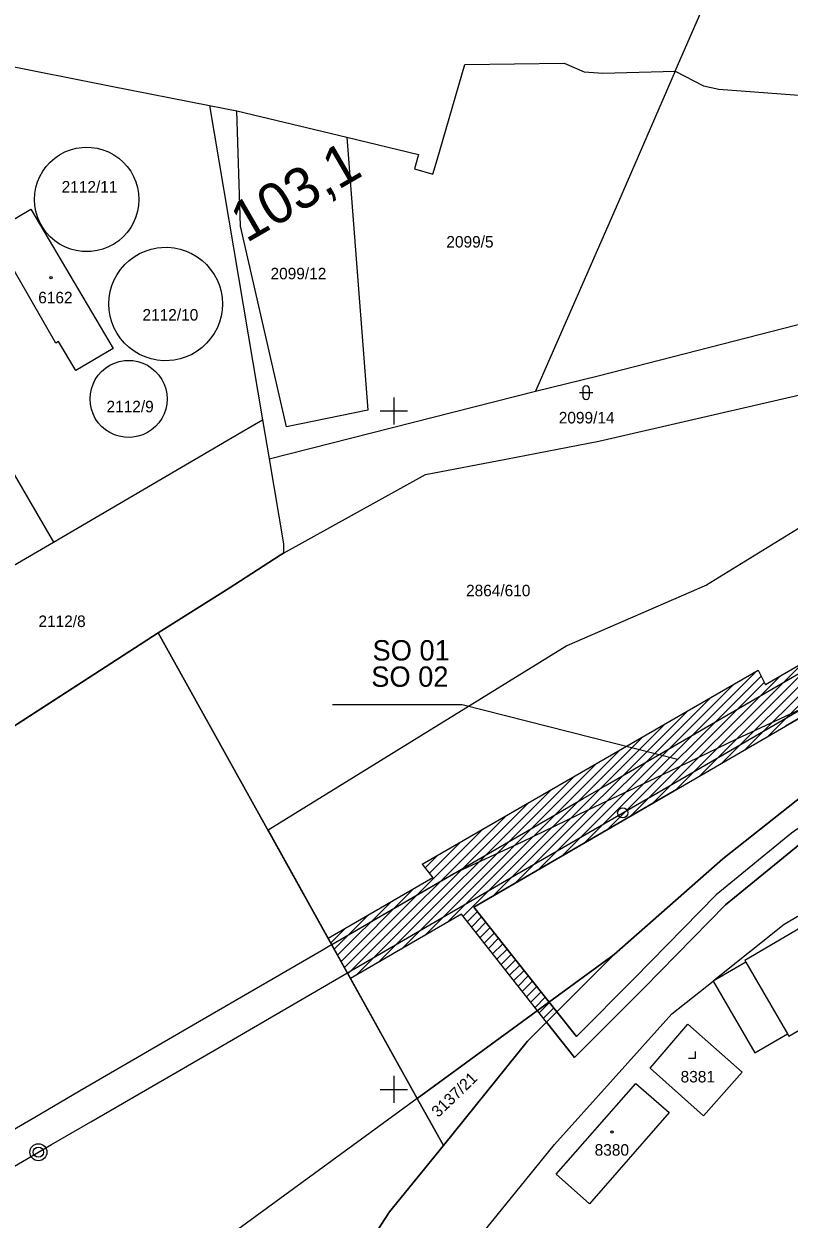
# Model space of a CAD drawing. Extents: x -566165 to -565287, y -1203064 to -1202391.
# Drawn here: x -565854.5 to -565741.8, y -1202819.1 to -1202643 of the extents above; entities that cross this region are included whole.
import ezdxf

# ---------------------------------------------------------------- set-up
doc = ezdxf.new("R2010")
doc.units = 0
for name, color, linetype in [('CD', 7, 'Continuous'), ('Hranice parcel', 7, 'Continuous'), ('Parcelní čísla', 7, 'Continuous'), ('Popis PS SO', 7, 'Continuous'), ('SZDC', 7, 'Continuous'), ('VBř', 7, 'Continuous'), ('Vnitřní kresba', 7, 'Continuous'), ('Vrstva 1', 7, 'Continuous'), ('Vrstva 5', 7, 'Continuous'), ('Vrstva 7', 7, 'Continuous'), ('Značky budov', 7, 'Continuous'), ('Značky kultur', 7, 'Continuous'), ('ČD dotčená část', 7, 'Continuous'), ('ČD pro SŽDC', 7, 'Continuous')]:
    doc.layers.add(name, color=color, linetype=linetype)

msp = doc.modelspace()

# ---------------------------------------------------------------- linework, layer by layer
at = {"layer": 'CD'}
for p, q in [((-565767.54, -1202780.11), (-565775.99, -1202788.56)), ((-565775.99, -1202788.56), (-565777.51, -1202790.08))]:
    msp.add_line(p, q, dxfattribs=at)
for points in [[(-565834.73, -1202732.72), (-565824.28, -1202726.13), (-565816.76, -1202721.27), (-565816.24, -1202720.98), (-565795.32, -1202709.38), (-565783.5, -1202707.11), (-565769.79, -1202704.47), (-565716.98, -1202692.29), (-565668.65, -1202665.75), (-565651.82, -1202653.08), (-565584.94, -1202616.47), (-565582.08, -1202612.99), (-565579.05, -1202609.31), (-565569.85, -1202598.11), (-565567.82, -1202597.46), (-565565.95, -1202596.85), (-565564.75, -1202597.63), (-565564, -1202597.36)], [(-565608.23, -1202688.5), (-565651.3, -1202717.76), (-565670.03, -1202715.16), (-565703.34, -1202733.61), (-565726.67, -1202746.32), (-565751.56, -1202766.01), (-565767.54, -1202780.11), (-565780.3, -1202792.87), (-565792.68, -1202808.29), (-565796.55, -1202801.32), (-565834.73, -1202732.72), (-565824.28, -1202726.13), (-565816.76, -1202721.27), (-565816.24, -1202720.98), (-565795.32, -1202709.38), (-565783.5, -1202707.11), (-565769.79, -1202704.47), (-565716.98, -1202692.29), (-565668.65, -1202665.75), (-565651.82, -1202653.08), (-565584.94, -1202616.47)], [(-565536.63, -1202645.61), (-565545.69, -1202654.38), (-565570.41, -1202669.07), (-565591.05, -1202679), (-565608.23, -1202688.5), (-565651.3, -1202717.76), (-565670.03, -1202715.16), (-565703.34, -1202733.61), (-565726.67, -1202746.32), (-565751.56, -1202766.01), (-565767.54, -1202780.11)], [(-565792.68, -1202808.29), (-565796.55, -1202801.32), (-565834.73, -1202732.72)], [(-565777.51, -1202790.08), (-565780.3, -1202792.87), (-565792.68, -1202808.29)]]:
    msp.add_lwpolyline(points, dxfattribs=at)
at = {"layer": 'Hranice parcel'}
for p, q in [((-565865.64, -1202647.34), (-565841.64, -1202652.13)), ((-565841.64, -1202652.13), (-565827.18, -1202654.97)), ((-565827.18, -1202654.97), (-565819.36, -1202701.33)), ((-565827.18, -1202654.97), (-565823.11, -1202655.77)), ((-565823.11, -1202655.77), (-565806.91, -1202659.65)), ((-565806.91, -1202659.65), (-565806.03, -1202671.21)), ((-565869.42, -1202686.25), (-565850.16, -1202719.34)), ((-565818.39, -1202707.05), (-565779.12, -1202697.06)), ((-565819.36, -1202701.33), (-565818.39, -1202707.05)), ((-565816.24, -1202720.98), (-565795.32, -1202709.38)), ((-565871.58, -1202731.87), (-565850.16, -1202719.34)), ((-565816.76, -1202721.27), (-565824.28, -1202726.13)), ((-565816.24, -1202720.98), (-565816.76, -1202721.27)), ((-565824.28, -1202726.13), (-565834.73, -1202732.72)), ((-565834.73, -1202732.72), (-565860.68, -1202749.5)), ((-565834.73, -1202732.72), (-565796.55, -1202801.32)), ((-565796.55, -1202801.32), (-565767.54, -1202780.11)), ((-565796.55, -1202801.32), (-565823.01, -1202820.65)), ((-565792.68, -1202808.29), (-565796.55, -1202801.32))]:
    msp.add_line(p, q, dxfattribs=at)
for points in [[(-565758.54, -1202649.93), (-565730.78, -1202586.31), (-565729.37, -1202583)], [(-565806.91, -1202659.65), (-565796.35, -1202662.18), (-565796.97, -1202664.29), (-565794.25, -1202665.09), (-565793.63, -1202662.98), (-565789.57, -1202648.94)], [(-565789.57, -1202648.94), (-565774.89, -1202648.73), (-565771.98, -1202650.02), (-565769.24, -1202650.23), (-565758.54, -1202649.93)], [(-565758.54, -1202649.93), (-565766.93, -1202669.16), (-565779.12, -1202697.06)], [(-565758.54, -1202649.93), (-565754.38, -1202652.1), (-565752.11, -1202652.57)], [(-565752.11, -1202652.57), (-565725.23, -1202654.6), (-565712.28, -1202653.27), (-565708.87, -1202652.92), (-565685.27, -1202662.95)], [(-565806.03, -1202671.21), (-565803.86, -1202699.87), (-565815.82, -1202702.35), (-565822.57, -1202672.74), (-565823.11, -1202655.77)], [(-565852.95, -1202668.82), (-565852.9, -1202667.94), (-565852.75, -1202667.08), (-565852.5, -1202666.24), (-565852.16, -1202665.43), (-565851.73, -1202664.66), (-565851.22, -1202663.95), (-565850.62, -1202663.31), (-565849.96, -1202662.73), (-565849.24, -1202662.23), (-565848.46, -1202661.82), (-565847.65, -1202661.5), (-565846.8, -1202661.28), (-565845.93, -1202661.15), (-565845.45, -1202661.12), (-565844.57, -1202661.15), (-565843.7, -1202661.28), (-565842.85, -1202661.5), (-565842.04, -1202661.82), (-565841.26, -1202662.23), (-565840.54, -1202662.73), (-565839.88, -1202663.31), (-565839.28, -1202663.95), (-565838.77, -1202664.66), (-565838.34, -1202665.43), (-565838, -1202666.24), (-565837.75, -1202667.08), (-565837.6, -1202667.94), (-565837.55, -1202668.82), (-565837.6, -1202669.7), (-565837.75, -1202670.56), (-565838, -1202671.4), (-565838.34, -1202672.21), (-565838.77, -1202672.98), (-565839.28, -1202673.69), (-565839.88, -1202674.33), (-565840.54, -1202674.91), (-565841.26, -1202675.41), (-565842.04, -1202675.82), (-565842.85, -1202676.14), (-565843.7, -1202676.36), (-565844.57, -1202676.49), (-565845.05, -1202676.52), (-565845.93, -1202676.49), (-565846.8, -1202676.36), (-565847.65, -1202676.14), (-565848.46, -1202675.82), (-565849.24, -1202675.41), (-565849.96, -1202674.91), (-565850.62, -1202674.33), (-565851.22, -1202673.69), (-565851.73, -1202672.98), (-565852.16, -1202672.21), (-565852.5, -1202671.4), (-565852.75, -1202670.56), (-565852.9, -1202669.7), (-565852.95, -1202668.82)], [(-565841.35, -1202690.81), (-565846.86, -1202694.06), (-565849.4, -1202689.75), (-565849.81, -1202689.99), (-565859.23, -1202673.66), (-565853.46, -1202670.26), (-565841.35, -1202690.81)], [(-565841.99, -1202684.23), (-565841.94, -1202683.32), (-565841.79, -1202682.41), (-565841.54, -1202681.53), (-565841.2, -1202680.69), (-565840.76, -1202679.88), (-565840.25, -1202679.13), (-565839.65, -1202678.43), (-565838.98, -1202677.81), (-565838.24, -1202677.26), (-565837.45, -1202676.8), (-565836.62, -1202676.43), (-565835.75, -1202676.15), (-565834.85, -1202675.96), (-565834.21, -1202675.89), (-565833.3, -1202675.88), (-565832.39, -1202675.96), (-565831.49, -1202676.15), (-565830.62, -1202676.43), (-565829.79, -1202676.8), (-565828.99, -1202677.26), (-565828.26, -1202677.81), (-565827.59, -1202678.43), (-565826.99, -1202679.13), (-565826.48, -1202679.88), (-565826.04, -1202680.69), (-565825.7, -1202681.53), (-565825.45, -1202682.41), (-565825.3, -1202683.32), (-565825.25, -1202684.23), (-565825.3, -1202685.14), (-565825.45, -1202686.05), (-565825.7, -1202686.93), (-565826.04, -1202687.78), (-565826.47, -1202688.58), (-565826.99, -1202689.34), (-565827.58, -1202690.03), (-565828.25, -1202690.65), (-565828.99, -1202691.2), (-565829.78, -1202691.67), (-565830.61, -1202692.04), (-565831.48, -1202692.32), (-565832.38, -1202692.51), (-565833.04, -1202692.58), (-565833.95, -1202692.59), (-565834.86, -1202692.51), (-565835.76, -1202692.32), (-565836.63, -1202692.04), (-565837.46, -1202691.67), (-565838.25, -1202691.2), (-565838.99, -1202690.65), (-565839.66, -1202690.03), (-565840.25, -1202689.34), (-565840.77, -1202688.58), (-565841.2, -1202687.78), (-565841.54, -1202686.93), (-565841.79, -1202686.05), (-565841.94, -1202685.14), (-565841.99, -1202684.23)], [(-565779.12, -1202697.06), (-565769.91, -1202694.83), (-565735.3, -1202685.95), (-565728.61, -1202684.07)], [(-565844.76, -1202698.23), (-565844.71, -1202697.48), (-565844.56, -1202696.74), (-565844.32, -1202696.03), (-565843.98, -1202695.35), (-565843.55, -1202694.73), (-565843.05, -1202694.17), (-565842.48, -1202693.68), (-565841.85, -1202693.27), (-565841.16, -1202692.95), (-565840.45, -1202692.72), (-565839.7, -1202692.58), (-565839.21, -1202692.55), (-565838.45, -1202692.58), (-565837.71, -1202692.72), (-565837, -1202692.95), (-565836.31, -1202693.27), (-565835.68, -1202693.68), (-565835.11, -1202694.17), (-565834.61, -1202694.73), (-565834.18, -1202695.35), (-565833.84, -1202696.03), (-565833.6, -1202696.74), (-565833.45, -1202697.48), (-565833.4, -1202698.23), (-565833.45, -1202698.98), (-565833.6, -1202699.72), (-565833.84, -1202700.43), (-565834.18, -1202701.11), (-565834.61, -1202701.73), (-565835.11, -1202702.29), (-565835.68, -1202702.78), (-565836.31, -1202703.19), (-565837, -1202703.51), (-565837.71, -1202703.74), (-565838.45, -1202703.88), (-565838.95, -1202703.91), (-565839.7, -1202703.88), (-565840.45, -1202703.74), (-565841.16, -1202703.51), (-565841.85, -1202703.19), (-565842.48, -1202702.78), (-565843.05, -1202702.29), (-565843.55, -1202701.73), (-565843.98, -1202701.11), (-565844.32, -1202700.43), (-565844.56, -1202699.72), (-565844.71, -1202698.98), (-565844.76, -1202698.23)], [(-565795.32, -1202709.38), (-565783.5, -1202707.11), (-565769.79, -1202704.47), (-565716.98, -1202692.29)], [(-565850.16, -1202719.34), (-565822.39, -1202703.1), (-565819.36, -1202701.33)], [(-565818.39, -1202707.05), (-565816.27, -1202719.58), (-565816.24, -1202720.98)], [(-565651.3, -1202717.76), (-565670.03, -1202715.16), (-565703.34, -1202733.61), (-565726.67, -1202746.32), (-565751.56, -1202766.01), (-565767.54, -1202780.11)], [(-565712.3, -1202757.94), (-565742.5, -1202775.71), (-565752.98, -1202784.04)], [(-565752.98, -1202784.04), (-565746.85, -1202794.61), (-565742.01, -1202791.8), (-565741.8, -1202792.15), (-565704.78, -1202770.64)], [(-565767.54, -1202780.11), (-565780.3, -1202792.87), (-565792.68, -1202808.29)], [(-565834.87, -1202948.36), (-565833.95, -1202929.34), (-565831.55, -1202914.98), (-565826.37, -1202896.2), (-565819.98, -1202876.61), (-565810.01, -1202854.24), (-565796, -1202832.35), (-565776.35, -1202808.14), (-565759.03, -1202788.85), (-565752.98, -1202784.04)], [(-565762.26, -1202796.85), (-565756.69, -1202790.4), (-565748.7, -1202797.44), (-565754.37, -1202803.92), (-565762.26, -1202796.85)], [(-565771.16, -1202816.85), (-565776.07, -1202812.49), (-565764.38, -1202799.11), (-565759.44, -1202803.42), (-565771.16, -1202816.85)], [(-565792.68, -1202808.29), (-565800.65, -1202818.05), (-565813.8, -1202838.35), (-565824.38, -1202859.45), (-565834.96, -1202885.73), (-565841.98, -1202913.48), (-565844.83, -1202934.31), (-565846.16, -1202954.76)]]:
    msp.add_lwpolyline(points, dxfattribs=at)
at = {"layer": 'Popis PS SO'}
msp.add_lwpolyline([(-565809.04, -1202743.26), (-565789.92, -1202743.26), (-565758.24, -1202751.33)], dxfattribs=at)
at = {"layer": 'SZDC'}
for points in [[(-566098.16, -1202902.15), (-566097.96, -1202902.03), (-566084.51, -1202894.21), (-566065.16, -1202881.19), (-566062.89, -1202879.66), (-566050.93, -1202871.86), (-566034.12, -1202860.89), (-566014.69, -1202848.22), (-565999.33, -1202838.2), (-565981.56, -1202826.61), (-565964.56, -1202815.52), (-565946.25, -1202803.07), (-565943.74, -1202801.57), (-565935.57, -1202796.69), (-565927.13, -1202791.65), (-565924.54, -1202790.1), (-565905.03, -1202778.89), (-565894.6, -1202771.96), (-565883.49, -1202764.57), (-565860.68, -1202749.5), (-565834.73, -1202732.72)], [(-565834.73, -1202732.72), (-565860.68, -1202749.5), (-565883.49, -1202764.57), (-565894.6, -1202771.96), (-565905.03, -1202778.89), (-565924.54, -1202790.1), (-565927.13, -1202791.65), (-565935.57, -1202796.69), (-565943.74, -1202801.57), (-565946.25, -1202803.07), (-565964.56, -1202815.52), (-565981.56, -1202826.61), (-565999.33, -1202838.2), (-566014.69, -1202848.22), (-566034.12, -1202860.89), (-566050.93, -1202871.86), (-566062.89, -1202879.66), (-566065.16, -1202881.19), (-566084.51, -1202894.21), (-566097.96, -1202902.03)], [(-565834.73, -1202732.72), (-565796.55, -1202801.32), (-565792.68, -1202808.29), (-565800.65, -1202818.05), (-565813.8, -1202838.35), (-565824.38, -1202859.45), (-565834.96, -1202885.73), (-565841.98, -1202913.48), (-565844.83, -1202934.31), (-565846.16, -1202954.76)], [(-565792.68, -1202808.29), (-565796.55, -1202801.32), (-565834.73, -1202732.72)], [(-565846.16, -1202954.76), (-565844.83, -1202934.31), (-565841.98, -1202913.48), (-565834.96, -1202885.73), (-565824.38, -1202859.45), (-565813.8, -1202838.35), (-565800.65, -1202818.05), (-565792.68, -1202808.29)]]:
    msp.add_lwpolyline(points, dxfattribs=at)
at = {"layer": 'VBř'}
for p, q in [((-565775.99, -1202788.56), (-565773.11, -1202792.19)), ((-565773.11, -1202792.19), (-565775.99, -1202788.56))]:
    msp.add_line(p, q, dxfattribs=at)
for points in [[(-565700.6, -1202736.02), (-565722.39, -1202751.33), (-565740.21, -1202763.83), (-565751.17, -1202772.78), (-565763.17, -1202785.08), (-565773.4, -1202795.31)], [(-565773.4, -1202795.31), (-565763.17, -1202785.08), (-565751.17, -1202772.78), (-565740.21, -1202763.83), (-565722.39, -1202751.33), (-565700.6, -1202736.02)], [(-565703.72, -1202735.77), (-565723.54, -1202749.69), (-565741.42, -1202762.23), (-565752.52, -1202771.3), (-565764.59, -1202783.67), (-565773.11, -1202792.19)], [(-565703.72, -1202735.77), (-565723.54, -1202749.69), (-565741.42, -1202762.23), (-565752.52, -1202771.3), (-565764.59, -1202783.67), (-565773.11, -1202792.19)], [(-565773.4, -1202795.31), (-565777.51, -1202790.08), (-565775.99, -1202788.56)], [(-565775.99, -1202788.56), (-565777.51, -1202790.08), (-565773.4, -1202795.31)]]:
    msp.add_lwpolyline(points, dxfattribs=at)
at = {"layer": 'Vnitřní kresba'}
for p, q in [((-565748.29, -1202780.97), (-565711.54, -1202759.22)), ((-565748.14, -1202781.23), (-565752.98, -1202784.04)), ((-565748.29, -1202780.97), (-565748.14, -1202781.23)), ((-565748.14, -1202781.23), (-565742.01, -1202791.8))]:
    msp.add_line(p, q, dxfattribs=at)
at = {"layer": 'Vrstva 1'}
for points in [[(-565758.48, -1202754.71), (-565721.48, -1202733.21), (-565716.28, -1202730.2), (-565687.52, -1202713.5), (-565681.68, -1202710.1), (-565634.86, -1202682.91)], [(-565809.14, -1202778.62), (-565772.11, -1202757.13), (-565768.53, -1202755.04), (-565741.86, -1202739.56), (-565718.89, -1202726.24), (-565715.99, -1202724.54), (-565690.27, -1202709.61), (-565684.03, -1202706), (-565661.11, -1202692.68)], [(-565875.64, -1202817.45), (-565857.12, -1202806.56), (-565852.87, -1202804.07), (-565846.29, -1202800.23), (-565828.61, -1202789.92), (-565810.66, -1202779.51), (-565809.41, -1202778.78), (-565809.14, -1202778.62), (-565791.15, -1202768.18), (-565781.12, -1202763.52), (-565771.26, -1202758.74), (-565767.75, -1202757.08), (-565765.33, -1202755.93), (-565759.34, -1202753.1), (-565749.49, -1202748.32), (-565739.46, -1202743.66), (-565721.48, -1202733.21)], [(-565873.31, -1202821.43), (-565854.72, -1202810.63), (-565850.44, -1202808.14), (-565844.65, -1202804.77), (-565825.76, -1202793.8), (-565806.93, -1202782.86), (-565788.47, -1202772.13), (-565782.81, -1202768.84), (-565766.29, -1202759.24), (-565758.48, -1202754.71)]]:
    msp.add_lwpolyline(points, dxfattribs=at)
at = {"layer": 'Vrstva 5'}
for p, q in [((-565800, -1202698), (-565800, -1202702)), ((-565802, -1202700), (-565798, -1202700)), ((-565800, -1202798), (-565800, -1202802)), ((-565802, -1202800), (-565798, -1202800))]:
    msp.add_line(p, q, dxfattribs=at)
at = {"layer": 'Vrstva 7'}
for centre, radius in [((-565766.29, -1202759.24), 0.75), ((-565852.37, -1202809.26), 1.25), ((-565852.37, -1202809.26), 0.752)]:
    msp.add_circle(centre, radius, dxfattribs=at)
at = {"layer": 'Značky budov'}
for centre in [(-565850.5, -1202680.36), (-565767.85, -1202806.29)]:
    msp.add_circle(centre, 0.175, dxfattribs=at)
at = {"layer": 'Značky kultur'}
for p, q in [((-565772.18, -1202696.79), (-565772.18, -1202697.79)), ((-565771.18, -1202697.79), (-565771.18, -1202696.79)), ((-565772.68, -1202697.29), (-565770.68, -1202697.29)), ((-565756.59, -1202795.42), (-565755.59, -1202795.42)), ((-565755.59, -1202795.42), (-565755.59, -1202794.42))]:
    msp.add_line(p, q, dxfattribs=at)
for centre, start, end in [((-565771.68, -1202696.79), 0, 180), ((-565771.68, -1202697.79), 180, 359.9879)]:
    msp.add_arc(centre, 0.5, start, end, dxfattribs=at)
at = {"layer": 'ČD dotčená část'}
for p, q in [((-565744.93, -1202747.98), (-565726.33, -1202729.39)), ((-565748.3, -1202749.94), (-565729.7, -1202731.35)), ((-565751.67, -1202751.9), (-565733.07, -1202733.3)), ((-565755.04, -1202753.86), (-565736.45, -1202735.26)), ((-565758.41, -1202755.82), (-565739.82, -1202737.22)), ((-565795.85, -1202766.82), (-565746.33, -1202738.2)), ((-565771.9, -1202763.65), (-565746.64, -1202738.38)), ((-565768.53, -1202761.69), (-565745.91, -1202739.07)), ((-565761.79, -1202757.77), (-565743.19, -1202739.18)), ((-565746.33, -1202738.2), (-565745.27, -1202740.39)), ((-565775.27, -1202765.6), (-565749.99, -1202740.32)), ((-565765.16, -1202759.73), (-565745.45, -1202740.02)), ((-565778.65, -1202767.56), (-565753.33, -1202742.25)), ((-565782.02, -1202769.52), (-565756.68, -1202744.19)), ((-565785.39, -1202771.48), (-565760.03, -1202746.12)), ((-565789.81, -1202774.48), (-565763.38, -1202748.06)), ((-565792.13, -1202775.39), (-565766.73, -1202749.99)), ((-565795.51, -1202777.35), (-565770.08, -1202751.93)), ((-565798.88, -1202779.31), (-565773.43, -1202753.86)), ((-565802.25, -1202781.27), (-565776.78, -1202755.8)), ((-565805.62, -1202783.22), (-565780.13, -1202757.73)), ((-565806.77, -1202782.96), (-565783.48, -1202759.67)), ((-565807.28, -1202782.05), (-565786.83, -1202761.6)), ((-565794.8, -1202768.16), (-565790.18, -1202763.54)), ((-565795.42, -1202767.37), (-565793.53, -1202765.47)), ((-565807.78, -1202781.14), (-565797.14, -1202770.5)), ((-565808.29, -1202780.23), (-565800.51, -1202772.46)), ((-565808.79, -1202779.32), (-565803.88, -1202774.42)), ((-565789.19, -1202775.28), (-565787.7, -1202773.79)), ((-565788.56, -1202776.07), (-565787.07, -1202774.58)), ((-565787.94, -1202776.86), (-565786.45, -1202775.36)), ((-565787.32, -1202777.65), (-565785.82, -1202776.15)), ((-565809.3, -1202778.42), (-565807.26, -1202776.37)), ((-565786.69, -1202778.44), (-565785.2, -1202776.94)), ((-565786.07, -1202779.23), (-565784.57, -1202777.73)), ((-565785.45, -1202780.02), (-565783.95, -1202778.52)), ((-565784.82, -1202780.81), (-565783.32, -1202779.31)), ((-565784.2, -1202781.6), (-565782.7, -1202780.1)), ((-565783.58, -1202782.39), (-565782.07, -1202780.89)), ((-565782.95, -1202783.18), (-565781.45, -1202781.68)), ((-565782.33, -1202783.97), (-565780.82, -1202782.47)), ((-565781.71, -1202784.77), (-565780.2, -1202783.25)), ((-565781.08, -1202785.56), (-565779.57, -1202784.04)), ((-565780.46, -1202786.35), (-565778.95, -1202784.83)), ((-565779.84, -1202787.14), (-565778.32, -1202785.62)), ((-565779.21, -1202787.93), (-565777.69, -1202786.41)), ((-565778.59, -1202788.72), (-565777.07, -1202787.2)), ((-565777.97, -1202789.51), (-565776.44, -1202787.99))]:
    msp.add_line(p, q, dxfattribs=at)
for points in [[(-565758.03, -1202755.59), (-565788.22, -1202773.12), (-565775.99, -1202788.56), (-565788.22, -1202773.12), (-565721.02, -1202734.1), (-565715.78, -1202731.06), (-565742.32, -1202746.47), (-565715.78, -1202731.06), (-565718.16, -1202726.96), (-565688.54, -1202709.76), (-565689.54, -1202708.03), (-565745.27, -1202740.39)], [(-565795.85, -1202766.82), (-565794.27, -1202768.83), (-565809.66, -1202777.77)], [(-565775.99, -1202788.56), (-565777.51, -1202790.08), (-565790.05, -1202774.18), (-565806.38, -1202783.66), (-565809.66, -1202777.77)]]:
    msp.add_lwpolyline(points, dxfattribs=at)
at = {"layer": 'ČD pro SŽDC'}
for points in [[(-565563.53, -1202598.19), (-565564.75, -1202597.63), (-565565.61, -1202597.07), (-565565.95, -1202596.85), (-565566.05, -1202596.88), (-565567.82, -1202597.46), (-565569.85, -1202598.11), (-565579.05, -1202609.31), (-565582.08, -1202612.99), (-565584.94, -1202616.47), (-565578.25, -1202627.55), (-565602.22, -1202640.13), (-565651.5, -1202666.71), (-565690.86, -1202689.45), (-565697.77, -1202691.07), (-565753.97, -1202725.68), (-565774.54, -1202734.62), (-565818.54, -1202761.81)], [(-565563.53, -1202598.19), (-565564.75, -1202597.63), (-565565.61, -1202597.07), (-565565.95, -1202596.85), (-565566.05, -1202596.88), (-565567.82, -1202597.46), (-565569.85, -1202598.11), (-565579.05, -1202609.31), (-565582.08, -1202612.99), (-565584.94, -1202616.47), (-565578.25, -1202627.55), (-565602.22, -1202640.13), (-565651.5, -1202666.71), (-565690.86, -1202689.45), (-565697.77, -1202691.07), (-565753.97, -1202725.68), (-565774.54, -1202734.62), (-565818.54, -1202761.81)], [(-565818.54, -1202761.81), (-565796.55, -1202801.32), (-565767.54, -1202780.11), (-565751.56, -1202766.01), (-565726.67, -1202746.32), (-565725.94, -1202745.92), (-565703.34, -1202733.61), (-565670.03, -1202715.16), (-565651.3, -1202717.76), (-565608.23, -1202688.5), (-565591.05, -1202679), (-565570.41, -1202669.07), (-565545.69, -1202654.38), (-565536.63, -1202645.61)], [(-565818.54, -1202761.81), (-565796.55, -1202801.32), (-565767.54, -1202780.11), (-565751.56, -1202766.01), (-565726.67, -1202746.32), (-565725.94, -1202745.92), (-565703.34, -1202733.61), (-565670.03, -1202715.16), (-565651.3, -1202717.76), (-565608.23, -1202688.5), (-565591.05, -1202679), (-565570.41, -1202669.07), (-565545.69, -1202654.38), (-565536.63, -1202645.61)]]:
    msp.add_lwpolyline(points, dxfattribs=at)
msp.add_lwpolyline([(-565767.54, -1202780.11), (-565796.55, -1202801.32), (-565792.68, -1202808.29), (-565780.3, -1202792.87)], close=True, dxfattribs=at)

# ---------------------------------------------------------------- texts
at = {"layer": 'Parcelní čísla'}
for s, p in [('2112/11', (-565848.94, -1202667.81)), ('2099/5', (-565792.27, -1202675.92)), ('2099/12', (-565818.17, -1202680.6)), ('6162', (-565852.39, -1202684.14)), ('2112/10', (-565837.03, -1202686.68)), ('2112/9', (-565842.33, -1202700.2)), ('2099/14', (-565775.71, -1202701.84)), ('2864/610', (-565789.37, -1202727.32)), ('2112/8', (-565852.36, -1202731.85)), ('8381', (-565757.76, -1202798.98)), ('8380', (-565770.42, -1202809.77))]:
    msp.add_text(s, height=1.7, dxfattribs=at).set_placement(p)
msp.add_text('3137/21', height=1.7, rotation=44, dxfattribs=at).set_placement((-565793.47, -1202804.23))
at = {"layer": 'Popis PS SO'}
for s, p in [('SO 01', (-565803.14, -1202736.78)), ('SO 02', (-565803.33, -1202740.66))]:
    msp.add_text(s, height=3, dxfattribs=at).set_placement(p)
at = {"layer": 'Vrstva 7'}
msp.add_text('103,1', height=6, rotation=30.1455, dxfattribs=at).set_placement((-565821.72, -1202675.3))

doc.saveas('drawing.dxf')
